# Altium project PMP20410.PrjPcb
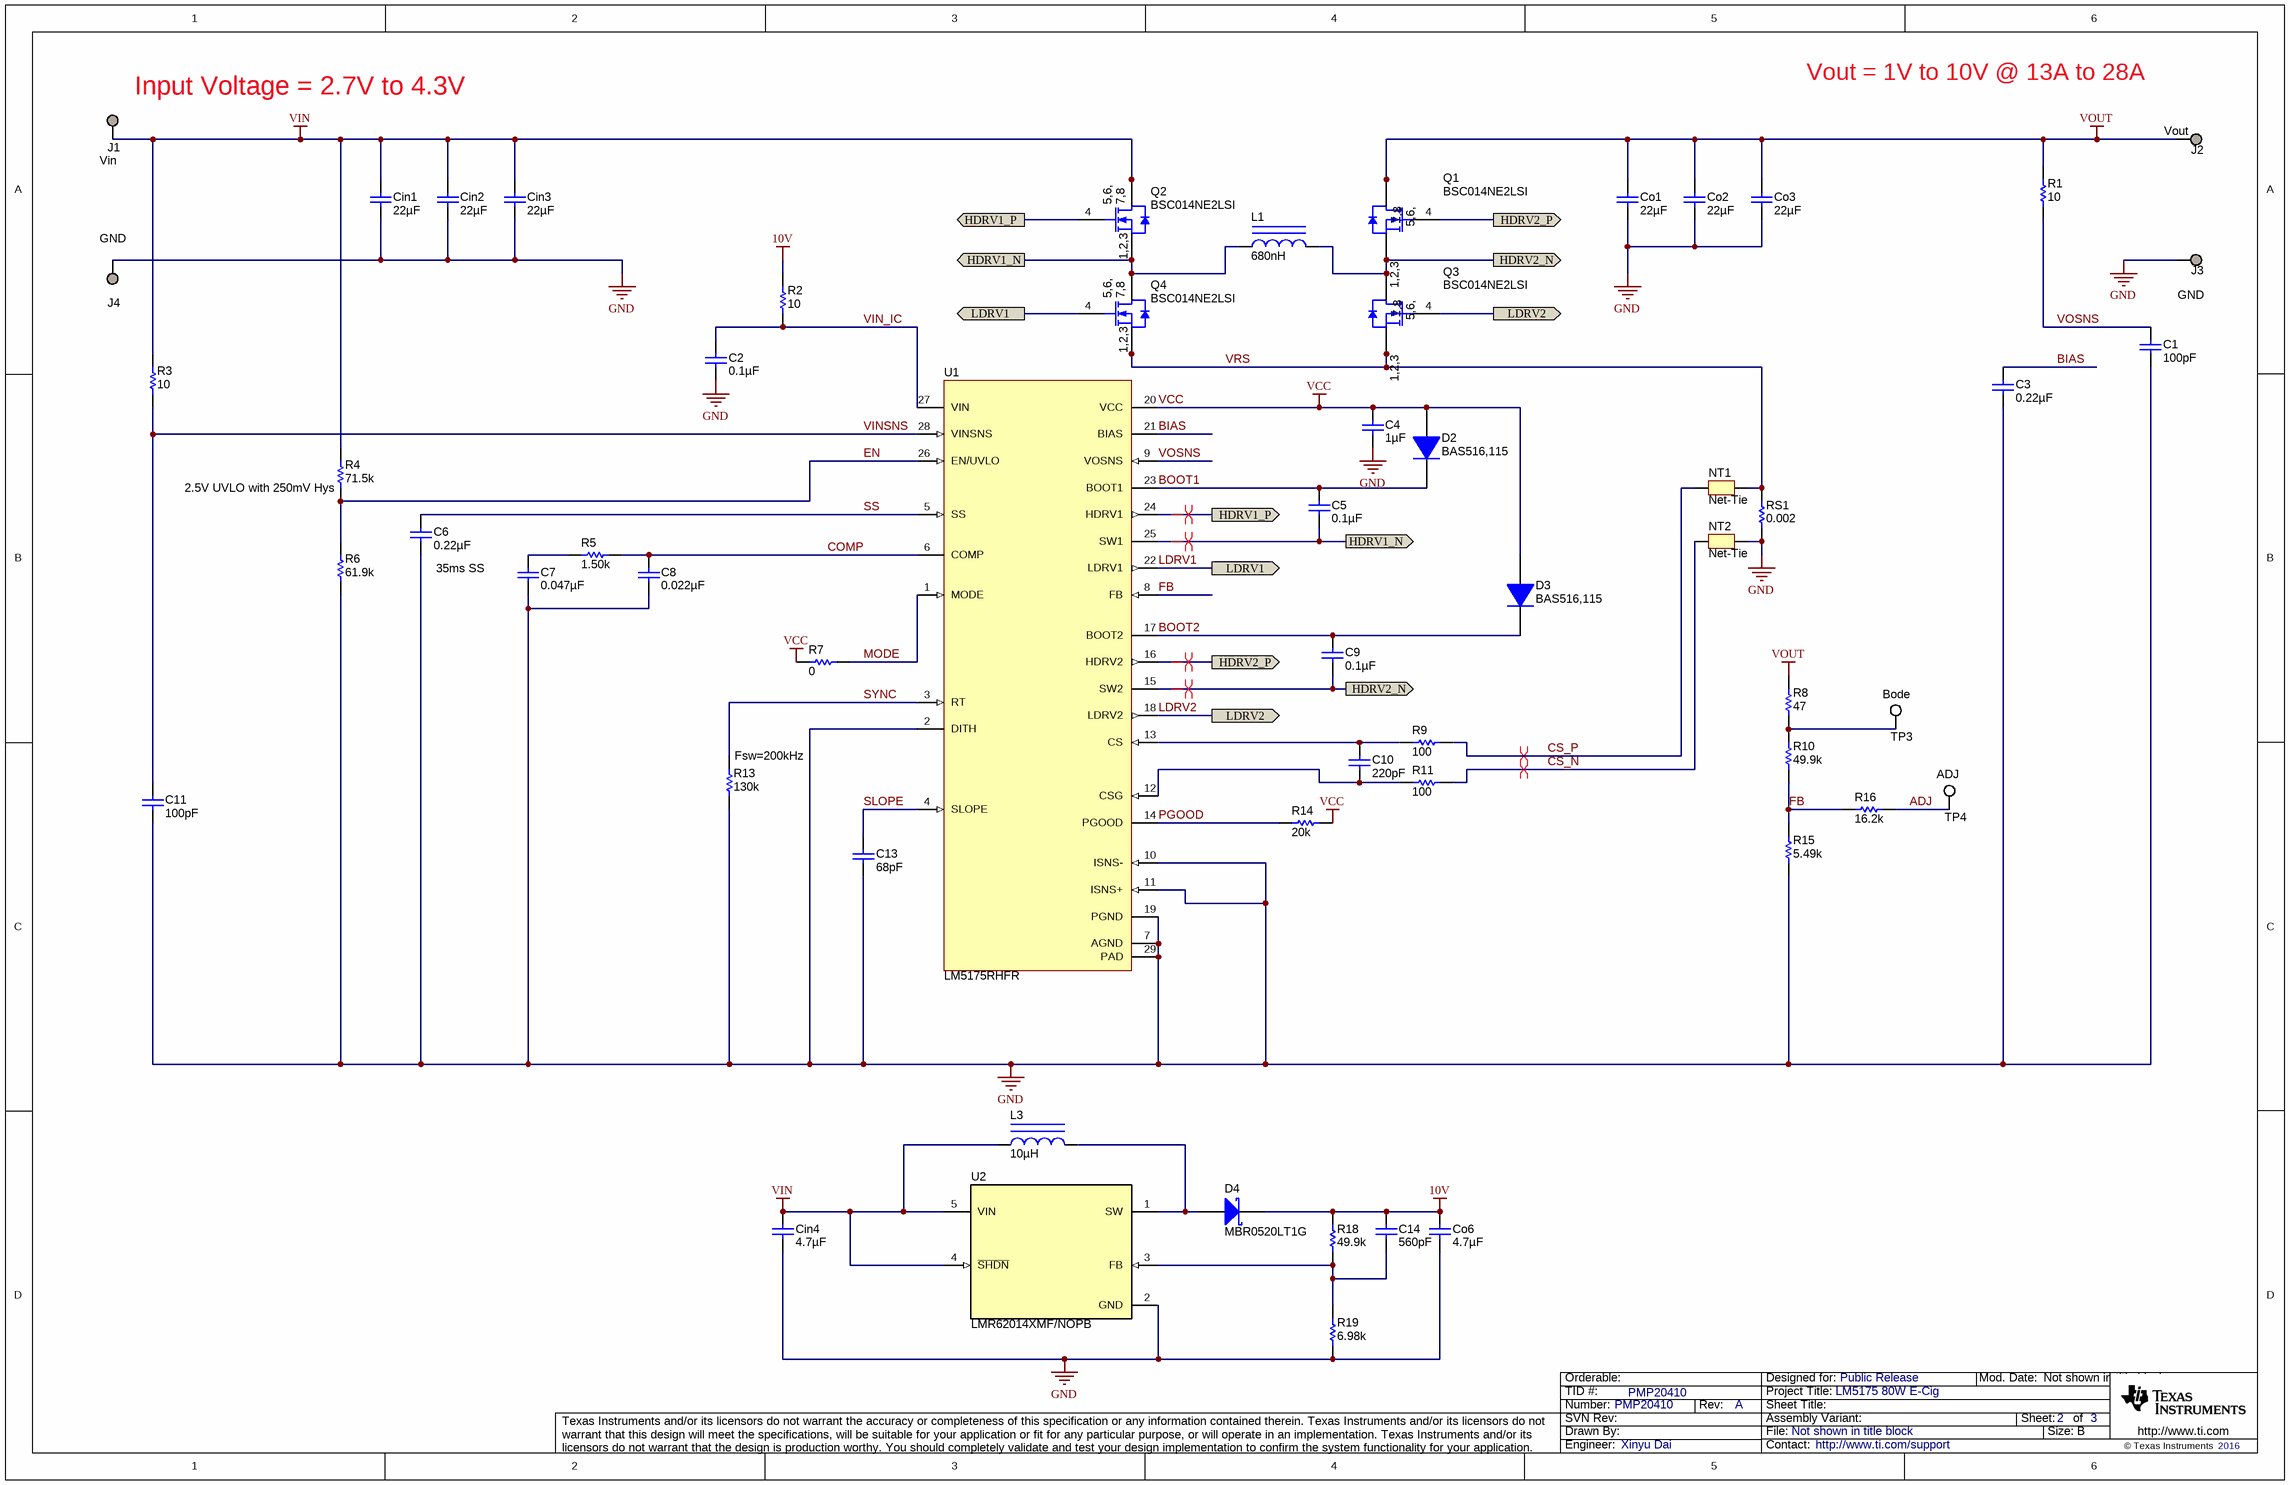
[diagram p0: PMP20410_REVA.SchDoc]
TID: PMP20410; TechSupport: http://www.ti.com/support; SCH_Rev: A; PRJ_Title: LM5175 80W E-Cig; PRJ_Number: PMP20410; PRJ_Engineer: Xinyu Dai; PRJ_Customer: Public Release; PCB_Rev: A; PCB_Layout: Xinyu Dai; CopyrightYear: 2016
2 sheets, 66 parts. Net scope: flat (ports and power ports of the same name join across sheets).
Board file: PMP20410_REVA.PcbDoc
Sheets:
  PMP20410_REVA.SchDoc
  PMP20410_REVA_Hardware.SchDoc

## Sheet PMP20410_REVA.SchDoc
size 431 x 279 mm; Date: Not shown in title block; ApprovedBy: Not shown in title block; CheckedBy: Not shown in title block; Author: Not shown in title block; CompanyName: Not shown in title block; Engineer: Not shown in title block; Organization: Not shown in title block; Address1: Not shown in title block; Address2: Not shown in title block; Address3: Not shown in title block; Address4: Not shown in title block; DocumentNumber: 1; Revision: Use project parameter SCH_Rev; SheetNumber: 2; SheetTotal: 3; PageSetup: Record=PageOptions¦CenterHorizontal=True¦CenterVertical=True¦PrintScale=1.00¦XCorrection=1.00¦YCorrection=1.00¦PrintKind=0¦BorderSize=5000000¦LeftOffset=0¦BottomOffset=0¦Orientation=2¦PaperLength=1000¦PaperWidth=1000¦Scale=100¦PaperSource=15¦PrintQuality=600¦MediaType=1¦DitherType=10¦PaperKind=Letter¦PrintScaleMode=1

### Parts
C1  ValueDisplayed: 100pF  [0402L]  (hidden comment: CC0402KRX7R9BB101)
C2  ValueDisplayed: 0.1µF  [0402L]  (hidden comment: GCM155R71H104KE02D)
C3  ValueDisplayed: 0.22µF  [0402L]  (hidden comment: C1005X5R1E224M050BC)
C4  ValueDisplayed: 1µF  [0402L]  (hidden comment: C1005X5R1C105K050BC)
C5  ValueDisplayed: 0.1µF  [0402L]  (hidden comment: GCM155R71H104KE02D)
C6  ValueDisplayed: 0.22µF  [0402L]  (hidden comment: C1005X5R1E224M050BC)
C7  ValueDisplayed: 0.047µF  [0402L]  (hidden comment: GRM155R71E473KA88D)
C8  ValueDisplayed: 0.022µF  [0402L]  (hidden comment: GRM155R71E223KA61D)
C9  ValueDisplayed: 0.1µF  [0402L]  (hidden comment: GCM155R71H104KE02D)
C10  ValueDisplayed: 220pF  [0402L]  (hidden comment: C1005X7R1H221K)
C11  ValueDisplayed: 100pF  [0402L]  (hidden comment: CC0402KRX7R9BB101)
C13  ValueDisplayed: 68pF  [0402L]  (hidden comment: GRM1555C1H680JA01D)
C14  ValueDisplayed: 560pF  [0402L]  (hidden comment: GRM155R71H561KA01D)
Cin1  ValueDisplayed: 22µF  [1206_180]  (hidden comment: GRM31CR71A226ME15L)
Cin2  ValueDisplayed: 22µF  [1206_180]  (hidden comment: GRM31CR71A226ME15L)
Cin3  ValueDisplayed: 22µF  [1206_180]  (hidden comment: GRM31CR71A226ME15L)
Cin4  ValueDisplayed: 4.7µF  [0805L]  (hidden comment: GRM21BR71C475KA73L)
Co1  ValueDisplayed: 22µF  [1210_270L]  (hidden comment: GRM32ER71E226KE15L)
Co2  ValueDisplayed: 22µF  [1210_270L]  (hidden comment: GRM32ER71E226KE15L)
Co3  ValueDisplayed: 22µF  [1210_270L]  (hidden comment: GRM32ER71E226KE15L)
Co6  ValueDisplayed: 4.7µF  [0805L]  (hidden comment: GRM21BR71C475KA73L)
D2  BAS516,115  [SOD-523]
D3  BAS516,115  [SOD-523]
D4  MBR0520LT1G  [SOD-123]
J1  Vin  [Keystone1598-2]
J2  Vout  [Keystone1598-2]
J3  GND  [Keystone1598-2]
J4  GND  [Keystone1598-2]
L1  ValueDisplayed: 680nH  [IHLP-5050FD]  (hidden comment: IHLP5050FDERR68M01)
L3  ValueDisplayed: 10µH  [LQH3NP_G0]  (hidden comment: LQH3NPN100NG0)
NT1  Net-Tie  [Net-Tie_10mil]  (net tie, no BOM)
NT2  Net-Tie  [Net-Tie_10mil]  (net tie, no BOM)
Q1  BSC014NE2LSI  [PG-TDSON-8]
Q2  BSC014NE2LSI  [PG-TDSON-8]
Q3  BSC014NE2LSI  [PG-TDSON-8]
Q4  BSC014NE2LSI  [PG-TDSON-8]
R1  ValueDisplayed: 10  [0402L]  (hidden comment: CRCW040210R0JNED)
R2  ValueDisplayed: 10  [0402L]  (hidden comment: CRCW040210R0JNED)
R3  ValueDisplayed: 10  [0402L]  (hidden comment: CRCW040210R0JNED)
R4  ValueDisplayed: 71.5k  [0402L]  (hidden comment: CRCW040271K5FKED)
R5  ValueDisplayed: 1.50k  [0402L]  (hidden comment: CRCW04021K50FKED)
R6  ValueDisplayed: 61.9k  [0402L]  (hidden comment: CRCW040261K9FKED)
R7  ValueDisplayed: 0  [0402L]  (hidden comment: CRCW04020000Z0ED)
R8  ValueDisplayed: 47  [0402L]  (hidden comment: CRCW040247R0JNED)
R9  ValueDisplayed: 100  [0402L]  (hidden comment: CRCW0402100RFKED)
R10  ValueDisplayed: 49.9k  [0402L]  (hidden comment: CRCW040249K9FKED)
R11  ValueDisplayed: 100  [0402L]  (hidden comment: CRCW0402100RFKED)
R13  ValueDisplayed: 130k  [0402L]  (hidden comment: CRCW0402130KFKED)
R14  ValueDisplayed: 20k  [0402L]  (hidden comment: CRCW040220K0JNED)
R15  ValueDisplayed: 5.49k  [0402L]  (hidden comment: CRCW04025K49FKED)
R16  ValueDisplayed: 16.2k  [0402L]  (hidden comment: CRCW040216K2FKED)
R18  ValueDisplayed: 49.9k  [0402L]  (hidden comment: CRCW040249K9FKED)
R19  ValueDisplayed: 6.98k  [0402L]  (hidden comment: CRCW04026K98FKED)
RS1  ValueDisplayed: 0.002  [FSCL76]  (hidden comment: FCSL76R002GER)
TP3  Bode  [Keystone5002]
TP4  ADJ  [Keystone5002]
U1  LM5175RHFR  [RHF0028A]
U2  LMR62014XMF/NOPB  [DBV0005A_N]

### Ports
HDRV1_N, HDRV1_P (out), HDRV2_N, HDRV2_P (out), LDRV1 (out), LDRV2 (out)

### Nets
10V: C14.1 Co6.1 D4.1(K) R2.2 R18.2
GND: C1.2 C2.2 C3.2 C4.2 C6.2 C7.2 C8.2 C11.1 C13.2 Cin1.2 Cin2.2 Cin3.2 Cin4.2 Co1.2 Co2.2 Co3.2 Co6.2 J3.1 J4.1 NT2.1 R6.1 R13.1 R15.1 R19.1 RS1.1 U1.2(DITH) U1.7(AGND) U1.10(ISNS-) U1.11(ISNS+) U1.19(PGND) U1.29(PAD) U2.2(GND)
VCC: C4.1 D2.2(A) D3.2(A) R7.2 R14.2 U1.20(VCC)
VIN: Cin1.1 Cin2.1 Cin3.1 Cin4.1 J1.1 L3.1 Q2.5(D) Q2.6(D) Q2.7(D) Q2.8(D) Q2.9(D) R3.1 R4.2 U2.4(~{SHDN}) U2.5(VIN)
VOUT: Co1.1 Co2.1 Co3.1 J2.1 Q1.5(D) Q1.6(D) Q1.7(D) Q1.8(D) Q1.9(D) R1.2 R8.1
ADJ: R16.1 TP4.1
BIAS: C3.1 U1.21(BIAS)
BOOT1: C5.1 D2.1(K) U1.23(BOOT1)
BOOT2: C9.2 D3.1(K) U1.17(BOOT2)
COMP: C8.1 R5.2 U1.6(COMP)
CS_N: NT2.2 R11.2
CS_P: NT1.2 R9.2
EN: R4.1 R6.2 U1.26(EN/UVLO)
FB: R10.1 R15.2 R16.2 U1.8(FB)
HDRV1_N: C5.2 L1.1 Q2.1(S) Q2.2(S) Q2.3(S) Q4.5(D) Q4.6(D) Q4.7(D) Q4.8(D) Q4.9(D) U1.25(SW1) ; port HDRV1_N
HDRV1_P: Q2.4(G) U1.24(HDRV1) ; port HDRV1_P
HDRV2_N: C9.1 L1.2 Q1.1(S) Q1.2(S) Q1.3(S) Q3.5(D) Q3.6(D) Q3.7(D) Q3.8(D) Q3.9(D) U1.15(SW2) ; port HDRV2_N
HDRV2_P: Q1.4(G) U1.16(HDRV2) ; port HDRV2_P
LDRV1: Q4.4(G) U1.22(LDRV1) ; port LDRV1
LDRV2: Q3.4(G) U1.18(LDRV2) ; port LDRV2
MODE: R7.1 U1.1(MODE)
PGOOD: R14.1 U1.14(PGOOD)
SLOPE: C13.1 U1.4(SLOPE)
SS: C6.1 U1.5(SS)
SYNC: R13.2 U1.3(RT)
VIN_IC: C2.1 R2.1 U1.27(VIN)
VINSNS: C11.2 R3.2 U1.28(VINSNS)
VOSNS: C1.1 R1.1 U1.9(VOSNS)
VRS: NT1.1 Q3.1(S) Q3.2(S) Q3.3(S) Q4.1(S) Q4.2(S) Q4.3(S) RS1.2
NetC7_1: C7.1 R5.1
NetC10_1: C10.1 R9.1 U1.13(CS)
NetC10_2: C10.2 R11.1 U1.12(CSG)
NetC14_2: C14.2 R18.1 R19.2 U2.3(FB)
NetD4_2: D4.2(A) L3.2 U2.1(SW)
NetR8_2: R8.2 R10.2 TP3.1

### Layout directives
differential pair: CS_N, CS_P, HDRV1_N, HDRV1_P, HDRV2_N, HDRV2_P

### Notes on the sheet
- (near J1) Input Voltage = 2.7V to 4.3V
- Vout = 1V to 10V @ 13A to 28A
- (near R4) 2.5V UVLO with 250mV Hys
- (near C6) 35ms SS
- (near R13) Fsw=200kHz

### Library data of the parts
C1 C11 = CC0402KRX7R9BB101: CAP, CERM, 100 pF, 50 V, +/- 10%, X7R, 0402; Manufacturer: Yageo America; Polarized: N; CompType: Capacitor; Value: 100pF; U/M: EA; Cap_F: 0.0000000001; Tolerance_%: 10; Value1: Unknown; VDC_V: 50; Value2: 50V; TaMin_C: -55; TaMax_C: 125; Cap_Case: 0402; AEC Category: Q200
C2 C5 C9 = GCM155R71H104KE02D: CAP, CERM, 0.1 µF, 50 V, +/- 10%, X7R, AEC-Q200 Grade 1, 0402; Manufacturer: MuRata; Polarized: N; CompType: Capacitor; Value: 0.1uF; U/M: EA; Cap_F: 0.0000001; Tolerance_%: 10; Value1: Unknown; VDC_V: 50; Value2: 50V; TaMin_C: -55; TaMax_C: 125; Cap_Case: 0402; AEC Category: Q200; AEC Qualified: Y; AEC Grade: 1
C3 = C1005X5R1E224M050BC: CAP, CERM, 0.22 µF, 25 V, +/- 20%, X5R, 0402; Manufacturer: TDK; Polarized: N; CompType: Capacitor; Value: 0.22uF; U/M: EA; Cap_F: 0.00000022; Tolerance_%: 20; Value1: Unknown; VDC_V: 25; Value2: 25V; TaMin_C: -55; TaMax_C: 85; Cap_Case: 0402; AEC Category: Q200
C4 = C1005X5R1C105K050BC: CAP, CERM, 1 µF, 16 V, +/- 10%, X5R, 0402; Manufacturer: TDK; Polarized: N; CompType: Capacitor; Value: 1uF; U/M: EA; Cap_F: 0.000001; Tolerance_%: 10; Value1: Unknown; VDC_V: 16; Value2: 16V; TaMin_C: -55; TaMax_C: 85; Cap_Case: 0402; AEC Category: Q200
C6 = C1005X5R1E224M050BC: CAP, CERM, 0.22 µF, 25 V, +/- 20%, X5R, 0402; Manufacturer: TDK; Polarized: N; CompType: Capacitor; Value: 0.22uF; U/M: EA; Cap_F: 0.00000022; Tolerance_%: 20; Value1: Unknown; VDC_V: 25; Value2: 25V; TaMin_C: -55; TaMax_C: 85; Cap_Case: 0402; AEC Category: Q200; SizeArea_mm2: 0.5; SizeAreaWB_mm2: 3; SizeX_mm: 1; SizeZ_mm: 0.6
C7 = GRM155R71E473KA88D: CAP, CERM, 0.047 µF, 25 V, +/- 10%, X7R, 0402; Manufacturer: MuRata; Polarized: N; CompType: Capacitor; Value: 0.047uF; U/M: EA; Cap_F: 0.000000047; Tolerance_%: 10; Value1: Unknown; VDC_V: 25; Value2: 25V; TaMin_C: -55; TaMax_C: 125; Cap_Case: 0402; AEC Category: Q200
C8 = GRM155R71E223KA61D: CAP, CERM, 0.022 µF, 25 V, +/- 10%, X7R, 0402; Manufacturer: MuRata; Polarized: N; CompType: Capacitor; Value: 0.022uF; U/M: EA; Cap_F: 0.000000022; Tolerance_%: 10; Value1: Unknown; VDC_V: 25; Value2: 25V; TaMin_C: -55; TaMax_C: 125; Cap_Case: 0402; AEC Category: Q200; SizeArea_mm2: 0.5; SizeAreaWB_mm2: 3; SizeX_mm: 1; SizeZ_mm: 0.6
C10 = C1005X7R1H221K: CAP, CERM, 220 pF, 50 V, +/- 10%, X7R, 0402; Manufacturer: TDK; Polarized: N; CompType: Capacitor; Value: 220pF; U/M: EA; Cap_F: 0.00000000022; Tolerance_%: 10; ESR_ohm: 0.59; Value1: 0.59 ohm; VDC_V: 50; Value2: 50V; TaMin_C: -55; TaMax_C: 125; Cap_Case: 0402; AEC Category: Q200
C13 = GRM1555C1H680JA01D: CAP, CERM, 68 pF, 50 V, +/- 5%, C0G/NP0, 0402; Manufacturer: MuRata; Polarized: N; CompType: Capacitor; Value: 68pF; U/M: EA; Cap_F: 0.000000000068; Tolerance_%: 5; Value1: Unknown; VDC_V: 50; Value2: 50V; TaMin_C: -55; TaMax_C: 125; Cap_Case: 0402; AEC Category: Q200; SizeArea_mm2: 0.5; SizeAreaWB_mm2: 3; SizeX_mm: 1; SizeZ_mm: 0.6
C14 = GRM155R71H561KA01D: CAP, CERM, 560 pF, 50 V, +/- 10%, X7R, 0402; Manufacturer: MuRata; Polarized: N; CompType: Capacitor; Value: 560pF; U/M: EA; Cap_F: 0.00000000056; Tolerance_%: 10; Value1: Unknown; VDC_V: 50; Value2: 50V; TaMin_C: -55; TaMax_C: 125; Cap_Case: 0402; SizeArea_mm2: 0.5; SizeAreaWB_mm2: 3; SizeX_mm: 1; SizeZ_mm: 0.6; AEC Category: Q200
Cin1-Cin3 = GRM31CR71A226ME15L: CAP, CERM, 22 µF, 10 V, +/- 20%, X7R, 1206; Manufacturer: MuRata; Polarized: N; CompType: Capacitor; Value: 22uF; U/M: EA; Cap_F: 0.000022; Tolerance_%: 20; Value1: Unknown; VDC_V: 10; Value2: 10V; TaMin_C: -55; TaMax_C: 125; Cap_Case: 1206; AEC Category: Q200
Cin4 Co6 = GRM21BR71C475KA73L: CAP, CERM, 4.7 µF, 16 V, +/- 10%, X7R, 0805; Manufacturer: MuRata; Polarized: N; CompType: Capacitor; Value: 4.7uF; U/M: EA; Cap_F: 0.0000047; Tolerance_%: 10; ESR_ohm: 0.006; Value1: 0.006 ohm; VDC_V: 16; Value2: 16V; TaMin_C: -55; TaMax_C: 125; Cap_Case: 0805; AEC Category: Q200; SizeArea_mm2: 2.5; SizeAreaWB_mm2: 6.75; SizeX_mm: 2; SizeY_mm: 1.25; SizeZ_mm: 1.45
Co1-Co3 = GRM32ER71E226KE15L: CAP, CERM, 22 µF, 25 V, +/- 10%, X7R, 1210; Manufacturer: MuRata; Polarized: N; CompType: Capacitor; Value: 22uF; U/M: EA; Cap_F: 0.000022; Tolerance_%: 10; Value1: Unknown; VDC_V: 25; Value2: 25V; TaMin_C: -55; TaMax_C: 125; Cap_Case: 1210; AEC Category: Q200; SizeArea_mm2: 8; SizeAreaWB_mm2: 14.7; SizeX_mm: 3.2; SizeY_mm: 2.5; SizeZ_mm: 2.7
D2 D3 = BAS516,115: Diode, Switching, 100V, 0.25A, SOD-523; Manufacturer: NXP Semiconductor; U/M: EA; Vf_V: 1.25; Value2: 1.25V; Io_A: 0.25; Vr_V: 100; TJmax_C: 150
D4 = MBR0520LT1G: Diode, Schottky, 20 V, 0.5 A, SOD-123; Manufacturer: ON Semiconductor; U/M: EA; Vf_V: 0.385; Value: 20V; Value1: 0.5A; Value2: 0.385V; Io_A: 0.5; Vr_V: 20; TJmax_C: 125; RJC_CperW: 150; SizeAreaWB_mm2: 13.095; SizeArea_mm2: 6.545; SizeX_mm: 3.85; SizeY_mm: 1.7; SizeZ_mm: 1.35; AEC Category: Q101
J1-J4 = 1598-2: Terminal, Turret, TH, Triple; Manufacturer: Keystone; CompType: Turret Terminal
L1 = IHLP5050FDERR68M01: Inductor, Shielded, Powdered Iron, 680 nH, 35 A, 0.0016 ohm, SMD; Manufacturer: Vishay-Dale; Value: 680nH; Ind_H: 680.0E-9; Imax_A: 35; Irms: 35A @ 40C rise; Isat: 60A @ 20% inductance drop; DCR_ohm: 0.0016; Value2: 35A; AEC Category: Q200
L3 = LQH3NPN100NG0: Inductor, Wirewound, Ferrite, 10 µH, 0.5 A, 0.57 ohm, SMD; Manufacturer: MuRata; Value: 10uH; Ind_H: 10.0E-6; Imax_A: 0.5; Irms: 0.63A @ 40C rise; Isat: 0.5A @ 30% inductance drop; DCR_ohm: 0.57; Value2: 0.5A; AEC Category: Q200
NT1 NT2 = Net-Tie: Single point connection between nets.; SymbolCreator: codlsc
Q1-Q4 = BSC014NE2LSI: MOSFET, N-CH, 25 V, 33 A, PG-TDSON-8; Manufacturer: Infineon Technologies; Alternate Manufacturer: None; U/M: EA; ChType: N; Value: 25V; VdsMax_V: 25; Value1: 0.002 ohm; Rdson45_ohm: 0.002; Value2: 39 nC; QgTyp_nC: 39; Vgs_V: 20; IdsMax_A: 33; AEC Category: Q101; SizeAreaWB_mm2: 55.131; SizeArea_mm2: 29.351; SizeX_mm: 5.99; SizeY_mm: 4.9; SizeZ_mm: 1.12
R1 = CRCW040210R0JNED: RES, 10, 5%, 0.063 W, 0402; Manufacturer: Vishay-Dale; CompType: Resistor; Value_Code: 10R0; Tolerance_%: 5; Power_W: 0.063; Value2: 0.063W; VDC_V: 50; TempCo: 200 ppm/C; EIA_Code: E24; U/M: EA; Value: 10; AEC Category: Q200
R2 R3 = CRCW040210R0JNED: RES, 10, 5%, 0.063 W, 0402; Manufacturer: Vishay-Dale; CompType: Resistor; Value: 10; Value_Code: 10R0; Tolerance_%: 5; Power_W: 0.063; Value2: 0.063W; VDC_V: 50; TempCo: 200 ppm/C; EIA_Code: E24; U/M: EA; AEC Category: Q200
R4 = CRCW040271K5FKED: RES, 71.5 k, 1%, 0.063 W, 0402; Manufacturer: Vishay-Dale; CompType: Resistor; Value: 71.5k; Res_ohm: 71500; Value_Code: 71k5; Tolerance_%: 1; Power_W: 0.063; Value2: 0.063W; VDC_V: 50; TempCo: 100 ppm/C; EIA_Code: E96; U/M: EA; AEC Category: Q200
R5 = CRCW04021K50FKED: RES, 1.50 k, 1%, 0.063 W, 0402; Manufacturer: Vishay-Dale; CompType: Resistor; Res_ohm: 1500; Value_Code: 1k50; Tolerance_%: 1; Power_W: 0.063; Value2: 0.063W; VDC_V: 50; TempCo: 100 ppm/C; EIA_Code: E96; U/M: EA; Value: 1.50k; AEC Category: Q200; SizeArea_mm2: 0.5; SizeZ_mm: 0.6
R6 = CRCW040261K9FKED: RES, 61.9 k, 1%, 0.063 W, 0402; Manufacturer: Vishay-Dale; CompType: Resistor; Value: 61.9k; Res_ohm: 61900; Value_Code: 61k9; Tolerance_%: 1; Power_W: 0.063; Value2: 0.063W; VDC_V: 50; TempCo: 100 ppm/C; EIA_Code: E96; U/M: EA; AEC Category: Q200; SizeArea_mm2: 0.5; SizeZ_mm: 0.6
R7 = CRCW04020000Z0ED: RES, 0, 5%, 0.063 W, 0402; Manufacturer: Vishay-Dale; CompType: Resistor; Value: 0; Value_Code: 0000; Tolerance_%: 5; Power_W: 0.063; Value2: 0.063W; VDC_V: 50; TempCo: 200 ppm/C; EIA_Code: E24; U/M: EA; AEC Category: Q200
R8 = CRCW040247R0JNED: RES, 47, 5%, 0.063 W, 0402; Manufacturer: Vishay-Dale; CompType: Resistor; Value: 47; Value_Code: 47R0; Tolerance_%: 5; Power_W: 0.063; Value2: 0.063W; VDC_V: 50; TempCo: 200 ppm/C; EIA_Code: E24; U/M: EA; AEC Category: Q200
R9 R11 = CRCW0402100RFKED: RES, 100, 1%, 0.063 W, 0402; Manufacturer: Vishay-Dale; CompType: Resistor; Value: 100; Value_Code: 100R; Tolerance_%: 1; Power_W: 0.063; Value2: 0.063W; VDC_V: 50; TempCo: 100 ppm/C; EIA_Code: E96; U/M: EA; AEC Category: Q200
R10 R18 = CRCW040249K9FKED: RES, 49.9 k, 1%, 0.063 W, 0402; Manufacturer: Vishay-Dale; CompType: Resistor; Value: 49.9k; Res_ohm: 49900; Value_Code: 49k9; Tolerance_%: 1; Power_W: 0.063; Value2: 0.063W; VDC_V: 50; TempCo: 100 ppm/C; EIA_Code: E96; U/M: EA; AEC Category: Q200
R13 = CRCW0402130KFKED: RES, 130 k, 1%, 0.063 W, 0402; Manufacturer: Vishay-Dale; CompType: Resistor; Value: 130k; Res_ohm: 130000; Tolerance_%: 1; Power_W: 0.063; Value2: 0.063W; VDC_V: 50; TempCo: 100 ppm/C; EIA_Code: E96; U/M: EA; AEC Category: Q200; SizeArea_mm2: 0.5; SizeZ_mm: 0.6
R14 = CRCW040220K0JNED: RES, 20 k, 5%, 0.063 W, 0402; Manufacturer: Vishay-Dale; CompType: Resistor; Value: 20k; Res_ohm: 20000; Value_Code: 20k0; Tolerance_%: 5; Power_W: 0.063; Value2: 0.063W; VDC_V: 50; TempCo: 200 ppm/C; EIA_Code: E24; U/M: EA; AEC Category: Q200
R15 = CRCW04025K49FKED: RES, 5.49 k, 1%, 0.063 W, 0402; Manufacturer: Vishay-Dale; CompType: Resistor; Value: 5.49k; Res_ohm: 5490; Value_Code: 5k49; Tolerance_%: 1; Power_W: 0.063; Value2: 0.063W; VDC_V: 50; TempCo: 100 ppm/C; EIA_Code: E96; U/M: EA; AEC Category: Q200
R16 = CRCW040216K2FKED: RES, 16.2 k, 1%, 0.063 W, 0402; Manufacturer: Vishay-Dale; CompType: Resistor; Value: 16.2k; Res_ohm: 16200; Value_Code: 16k2; Tolerance_%: 1; Power_W: 0.063; Value2: 0.063W; VDC_V: 50; TempCo: 100 ppm/C; EIA_Code: E96; U/M: EA; AEC Category: Q200
R19 = CRCW04026K98FKED: RES, 6.98 k, 1%, 0.063 W, 0402; Manufacturer: Vishay-Dale; CompType: Resistor; Value: 6.98k; Res_ohm: 6980; Value_Code: 6k98; Tolerance_%: 1; Power_W: 0.063; Value2: 0.063W; VDC_V: 50; TempCo: 100 ppm/C; EIA_Code: E96; U/M: EA; AEC Category: Q200; SizeArea_mm2: 0.5; SizeZ_mm: 0.6
RS1 = FCSL76R002GER: RES, 0.002, 2%, 3 W, 2.8x7.6x.7mm; Manufacturer: Ohmite; CompType: Resistor; Value: 0.002; Tolerance_%: 2; Power_W: 3; TempCo: 100 ppm/C; U/M: EA; Value_Code: 2L000; Value2: 3W; AEC Category: Q200; AEC Qualified: N; SizeArea_mm2: 28.88; SizeAreaWB_mm2: 55.68; SizeX_mm: 3.8; SizeY_mm: 7.6; SizeZ_mm: 0.7
TP3 TP4 = 5002: Test Point, Miniature, White, TH; Manufacturer: Keystone; CompType: Test Point Loop; ContactFinish: Silver
U1 = LM5175RHFR: 42-V Wide VIN Synchronous 4-Switch Buck-Boost Controller, RHF0028A; Alternate PartNumber: LM5175RHFT; Manufacturer: Texas Instruments; SymbolCreator: Altium; CompType: IC; U/M: EA
U2 = LMR62014XMF/NOPB: LMR62014 SIMPLE SWITCHER® 20Vout, 1.4 A Step-Up Voltage Regulator, DBV0005A; Manufacturer: Texas Instruments; SymbolCreator: Altium; SizeArea_mm2: 8.12; SizeAreaWB_mm2: 14.82; SizeX_mm: 2.8; SizeY_mm: 2.9; SizeZ_mm: 1.45; CompType: IC; U/M: EA

## Sheet PMP20410_REVA_Hardware.SchDoc
size 431 x 279 mm; Date: Not shown in title block; ApprovedBy: Not shown in title block; CheckedBy: Not shown in title block; Author: Not shown in title block; CompanyName: Not shown in title block; Engineer: Not shown in title block; Organization: Not shown in title block; Address1: Not shown in title block; Address2: Not shown in title block; Address3: Not shown in title block; Address4: Not shown in title block; DocumentNumber: 1; Revision: Use project parameter SCH_Rev; SheetNumber: 3; SheetTotal: 3; PageSetup: Record=PageOptions¦CenterHorizontal=True¦CenterVertical=True¦PrintScale=1.00¦XCorrection=1.00¦YCorrection=1.00¦PrintKind=0¦BorderSize=5000000¦LeftOffset=0¦BottomOffset=0¦Orientation=2¦PaperLength=1000¦PaperWidth=1000¦Scale=100¦PaperSource=15¦PrintQuality=600¦MediaType=1¦DitherType=10¦PaperKind=Letter¦PrintScaleMode=1
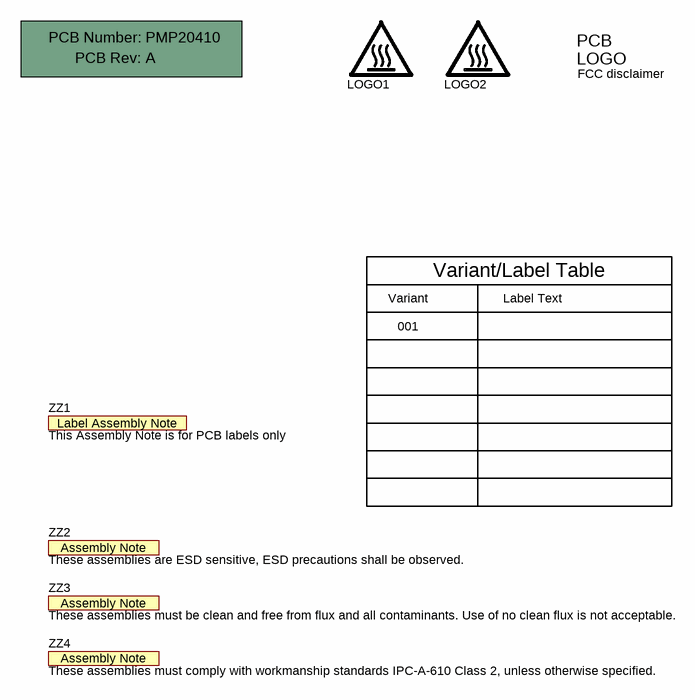
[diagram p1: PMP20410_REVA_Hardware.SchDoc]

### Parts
!PCB  Printed Circuit Board  (value not drawn)  (mechanical)
LOGO1  CAUTION HOT SURFACE  [IEC_HotSurface_Small]  (value not drawn)  (no BOM)
LOGO2  CAUTION HOT SURFACE  [IEC_HotSurface_Small]  (value not drawn)  (no BOM)
Logo3  FCC disclaimer  [FCC_disclaimer]  (no BOM)
ZZ1  This Assembly Note is for PCB labels only  [AssemblyNoteLabel]  (no BOM)
ZZ2  These assemblies are ESD sensitive, ESD precautions shall be observed.  [AssemblyNote]  (no BOM)
ZZ3  These assemblies must be clean and free from flux and all contaminants. Use of no clean flux is not acceptable.  [AssemblyNote]  (no BOM)
ZZ4  These assemblies must comply with workmanship standards IPC-A-610 Class 2, unless otherwise specified.  [AssemblyNote]  (no BOM)

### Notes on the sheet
- Variant
- Variant/Label Table
- Label Text
- 001

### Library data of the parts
!PCB = PCB: Manufacturer: Any; PartNumber: PMP20410; SymbolCreator: a0412235
LOGO1 LOGO2 = IEC_HotSurface: IEC 61010-1 Hot Surface Warning; SymbolCreator: a0412235
Logo3 = FCC_disclaimer: SymbolCreator: codlsc
ZZ1 = AssemblyNoteLabel: SymbolCreator: a0412235
ZZ2-ZZ4 = AssemblyNote: SymbolCreator: codlsc

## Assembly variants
001: not fitted FID1 FID2 FID3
